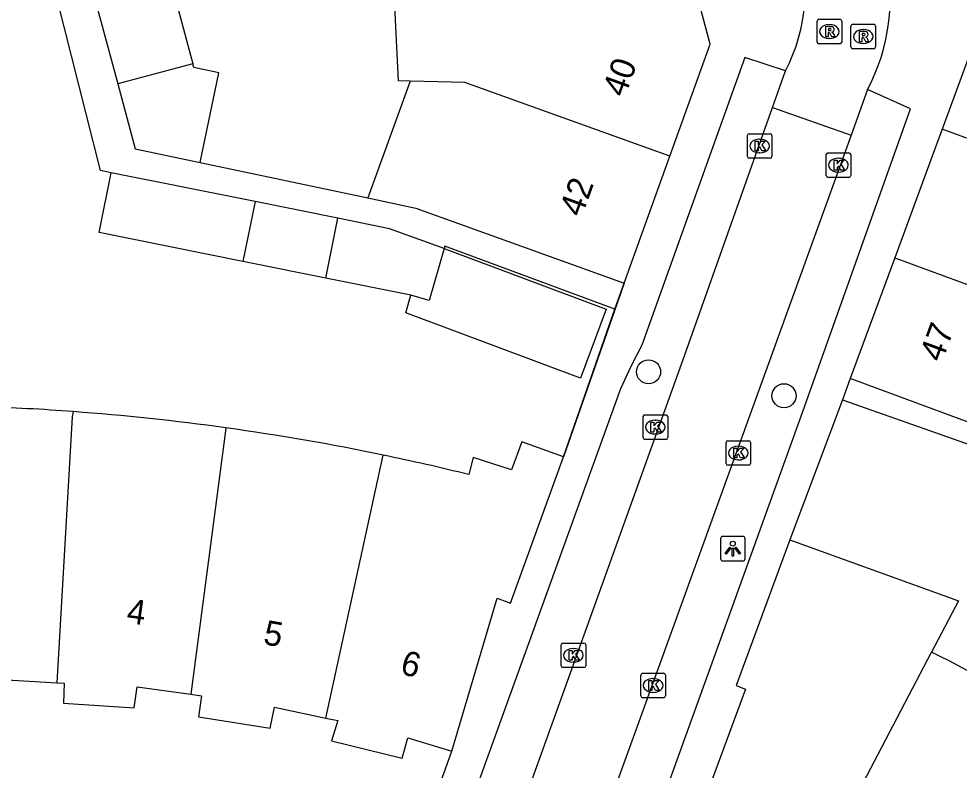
# Model space of a CAD drawing. Extents: x 162542 to 163144, y 380786 to 381511.
# Drawn here: x 162675.46 to 162713.73, y 380871.24 to 380901.83 of the extents above; entities that cross this region are included whole.
import ezdxf

# ---------------------------------------------------------------- set-up
doc = ezdxf.new("R2010")
doc.units = 0
for name, color, linetype in [('IMGEO_Boom', 7, 'Continuous'), ('IMGEO_Kolk', 7, 'Continuous'), ('IMGEO_Lichtpunt', 7, 'Continuous'), ('IMGEO_Muur', 7, 'Continuous'), ('IMGEO_Pand', 7, 'Continuous'), ('IMGEO_Pand_nummerreeks', 7, 'Continuous'), ('IMGEO_Rijbaan_lokaal_open', 7, 'Continuous'), ('IMGEO_Rioolput', 7, 'Continuous'), ('IMGEO_Voetpad_open', 7, 'Continuous')]:
    doc.layers.add(name, color=color, linetype=linetype)

msp = doc.modelspace()

# ---------------------------------------------------------------- linework, layer by layer
at = {"layer": 'IMGEO_Boom'}
for centre in [(162701.087, 380887.461), (162706.598, 380886.486)]:
    msp.add_circle(centre, 0.489, dxfattribs=at)
at = {"layer": 'IMGEO_Kolk'}
for p, q in [((162705.107, 380896.227), (162705.107, 380897.079)), ((162705.182, 380897.153), (162706.034, 380897.153)), ((162705.595, 380896.933), (162705.62, 380896.933)), ((162706.108, 380897.079), (162706.108, 380896.227)), ((162706.034, 380896.153), (162705.182, 380896.153)), ((162705.618, 380896.373), (162705.593, 380896.373)), ((162708.313, 380895.448), (162708.313, 380896.3)), ((162708.388, 380896.374), (162709.24, 380896.374)), ((162708.801, 380896.154), (162708.826, 380896.154)), ((162709.314, 380896.3), (162709.314, 380895.448)), ((162709.24, 380895.374), (162708.388, 380895.374)), ((162708.824, 380895.594), (162708.799, 380895.594)), ((162700.864, 380884.783), (162700.864, 380885.635)), ((162700.939, 380885.709), (162701.791, 380885.709)), ((162701.352, 380885.489), (162701.377, 380885.489)), ((162701.865, 380885.635), (162701.865, 380884.783)), ((162701.791, 380884.709), (162700.939, 380884.709)), ((162701.375, 380884.929), (162701.35, 380884.929)), ((162704.239, 380883.729), (162704.239, 380884.581)), ((162704.314, 380884.655), (162705.166, 380884.655)), ((162705.24, 380884.581), (162705.24, 380883.729)), ((162704.727, 380884.435), (162704.752, 380884.435)), ((162704.75, 380883.875), (162704.725, 380883.875)), ((162705.166, 380883.655), (162704.314, 380883.655)), ((162697.529, 380875.494), (162697.529, 380876.346)), ((162697.604, 380876.42), (162698.456, 380876.42)), ((162698.017, 380876.2), (162698.042, 380876.2)), ((162698.53, 380876.346), (162698.53, 380875.494)), ((162698.456, 380875.42), (162697.604, 380875.42)), ((162698.04, 380875.64), (162698.015, 380875.64)), ((162700.774, 380874.267), (162700.774, 380875.119)), ((162700.849, 380875.193), (162701.701, 380875.193)), ((162701.775, 380875.119), (162701.775, 380874.267)), ((162701.262, 380874.973), (162701.287, 380874.973)), ((162701.285, 380874.413), (162701.26, 380874.413)), ((162701.701, 380874.193), (162700.849, 380874.193))]:
    msp.add_line(p, q, dxfattribs=at)
for points in [[(162705.107, 380896.227), (162705.107, 380897.079)], [(162705.182, 380897.153), (162706.034, 380897.153)], [(162705.428, 380896.853), (162705.551, 380896.853), (162705.551, 380896.702), (162705.681, 380896.853), (162705.845, 380896.853), (162705.699, 380896.702), (162705.852, 380896.453), (162705.7, 380896.453), (162705.615, 380896.617), (162705.551, 380896.55), (162705.551, 380896.453), (162705.428, 380896.453), (162705.428, 380896.853)], [(162706.108, 380897.079), (162706.108, 380896.227)], [(162706.034, 380896.153), (162705.182, 380896.153)], [(162708.313, 380895.448), (162708.313, 380896.3)], [(162708.388, 380896.374), (162709.24, 380896.374)], [(162708.634, 380896.074), (162708.757, 380896.074), (162708.757, 380895.923), (162708.887, 380896.074), (162709.051, 380896.074), (162708.905, 380895.923), (162709.058, 380895.674), (162708.906, 380895.674), (162708.821, 380895.838), (162708.757, 380895.771), (162708.757, 380895.674), (162708.634, 380895.674), (162708.634, 380896.074)], [(162709.314, 380896.3), (162709.314, 380895.448)], [(162709.24, 380895.374), (162708.388, 380895.374)], [(162700.864, 380884.783), (162700.864, 380885.635)], [(162700.939, 380885.709), (162701.791, 380885.709)], [(162701.185, 380885.409), (162701.308, 380885.409), (162701.308, 380885.258), (162701.438, 380885.409), (162701.602, 380885.409), (162701.456, 380885.258), (162701.609, 380885.009), (162701.457, 380885.009), (162701.372, 380885.173), (162701.308, 380885.106), (162701.308, 380885.009), (162701.185, 380885.009), (162701.185, 380885.409)], [(162701.865, 380885.635), (162701.865, 380884.783)], [(162701.791, 380884.709), (162700.939, 380884.709)], [(162704.239, 380883.729), (162704.239, 380884.581)], [(162704.314, 380884.655), (162705.166, 380884.655)], [(162705.24, 380884.581), (162705.24, 380883.729)], [(162704.56, 380884.355), (162704.683, 380884.355), (162704.683, 380884.204), (162704.813, 380884.355), (162704.977, 380884.355), (162704.831, 380884.204), (162704.984, 380883.955), (162704.832, 380883.955), (162704.747, 380884.119), (162704.683, 380884.052), (162704.683, 380883.955), (162704.56, 380883.955), (162704.56, 380884.355)], [(162705.166, 380883.655), (162704.314, 380883.655)], [(162697.529, 380875.494), (162697.529, 380876.346)], [(162697.604, 380876.42), (162698.456, 380876.42)], [(162698.53, 380876.346), (162698.53, 380875.494)], [(162697.85, 380876.12), (162697.973, 380876.12), (162697.973, 380875.969), (162698.103, 380876.12), (162698.267, 380876.12), (162698.121, 380875.969), (162698.274, 380875.72), (162698.122, 380875.72), (162698.037, 380875.884), (162697.973, 380875.817), (162697.973, 380875.72), (162697.85, 380875.72), (162697.85, 380876.12)], [(162698.456, 380875.42), (162697.604, 380875.42)], [(162700.774, 380874.267), (162700.774, 380875.119)], [(162700.849, 380875.193), (162701.701, 380875.193)], [(162701.775, 380875.119), (162701.775, 380874.267)], [(162701.095, 380874.893), (162701.218, 380874.893), (162701.218, 380874.742), (162701.348, 380874.893), (162701.512, 380874.893), (162701.366, 380874.742), (162701.519, 380874.493), (162701.367, 380874.493), (162701.282, 380874.657), (162701.218, 380874.59), (162701.218, 380874.493), (162701.095, 380874.493), (162701.095, 380874.893)], [(162701.701, 380874.193), (162700.849, 380874.193)]]:
    msp.add_lwpolyline(points, dxfattribs=at)
for centre, start, end in [((162705.184, 380897.077), 91.552, 178.448), ((162705.184, 380897.077), 91.552, 178.448), ((162706.032, 380897.077), 1.552, 88.448), ((162706.032, 380897.077), 1.552, 88.448), ((162705.184, 380896.229), 181.552, 268.448), ((162705.184, 380896.229), 181.552, 268.448), ((162706.032, 380896.229), 271.552, 358.448), ((162706.032, 380896.229), 271.552, 358.448), ((162708.39, 380896.298), 91.552, 178.448), ((162708.39, 380896.298), 91.552, 178.448), ((162709.238, 380896.298), 1.552, 88.448), ((162709.238, 380896.298), 1.552, 88.448), ((162708.39, 380895.45), 181.552, 268.448), ((162708.39, 380895.45), 181.552, 268.448), ((162709.238, 380895.45), 271.552, 358.448), ((162709.238, 380895.45), 271.552, 358.448), ((162700.941, 380885.633), 91.552, 178.448), ((162700.941, 380885.633), 91.552, 178.448), ((162701.789, 380885.633), 1.552, 88.448), ((162701.789, 380885.633), 1.552, 88.448), ((162700.941, 380884.785), 181.552, 268.448), ((162700.941, 380884.785), 181.552, 268.448), ((162701.789, 380884.785), 271.552, 358.448), ((162701.789, 380884.785), 271.552, 358.448), ((162704.316, 380884.579), 91.552, 178.448), ((162704.316, 380884.579), 91.552, 178.448), ((162705.164, 380884.579), 1.552, 88.448), ((162705.164, 380884.579), 1.552, 88.448), ((162704.316, 380883.731), 181.552, 268.448), ((162704.316, 380883.731), 181.552, 268.448), ((162705.164, 380883.731), 271.552, 358.448), ((162705.164, 380883.731), 271.552, 358.448), ((162697.606, 380876.344), 91.552, 178.448), ((162697.606, 380876.344), 91.552, 178.448), ((162698.454, 380876.344), 1.552, 88.448), ((162698.454, 380876.344), 1.552, 88.448), ((162697.606, 380875.496), 181.552, 268.448), ((162697.606, 380875.496), 181.552, 268.448), ((162698.454, 380875.496), 271.552, 358.448), ((162698.454, 380875.496), 271.552, 358.448), ((162700.851, 380875.117), 91.552, 178.448), ((162700.851, 380875.117), 91.552, 178.448), ((162701.699, 380875.117), 1.552, 88.448), ((162701.699, 380875.117), 1.552, 88.448), ((162700.851, 380874.269), 181.552, 268.448), ((162700.851, 380874.269), 181.552, 268.448), ((162701.699, 380874.269), 271.552, 358.448), ((162701.699, 380874.269), 271.552, 358.448)]:
    msp.add_arc(centre, 0.0765, start, end, dxfattribs=at)
for centre, major_axis, ratio, start_param, end_param in [((162705.594, 380896.653), (-0.387, 0.002), 0.722429, 4.712389, 7.853982), ((162705.619, 380896.653), (-0.39, 0.002), 0.717154, 1.570796, 4.712389), ((162708.8, 380895.874), (-0.387, 0.002), 0.722429, 4.712389, 7.853982), ((162708.825, 380895.874), (-0.39, 0.002), 0.717154, 1.570796, 4.712389), ((162701.351, 380885.209), (-0.387, 0.002), 0.722429, 4.712389, 7.853982), ((162701.376, 380885.209), (-0.39, 0.002), 0.717154, 1.570796, 4.712389), ((162704.726, 380884.155), (-0.387, 0.002), 0.722429, 4.712389, 7.853982), ((162704.751, 380884.155), (-0.39, 0.002), 0.717154, 1.570796, 4.712389), ((162698.016, 380875.92), (-0.387, 0.002), 0.722429, 4.712389, 7.853982), ((162698.041, 380875.92), (-0.39, 0.002), 0.717154, 1.570796, 4.712389), ((162701.261, 380874.693), (-0.387, 0.002), 0.722429, 4.712389, 7.853982), ((162701.286, 380874.693), (-0.39, 0.002), 0.717154, 1.570796, 4.712389)]:
    msp.add_ellipse(centre, major_axis=major_axis, ratio=ratio, start_param=start_param, end_param=end_param, dxfattribs=at)
at = {"layer": 'IMGEO_Lichtpunt'}
for p, q in [((162704.917, 380880.76), (162704.109, 380880.76)), ((162704.917, 380880.76), (162704.109, 380880.76)), ((162704.015, 380880.665), (162704.015, 380879.858)), ((162704.015, 380880.665), (162704.015, 380879.858)), ((162705.011, 380879.858), (162705.011, 380880.665)), ((162705.011, 380879.858), (162705.011, 380880.665)), ((162704.109, 380879.764), (162704.917, 380879.764)), ((162704.109, 380879.764), (162704.917, 380879.764))]:
    msp.add_line(p, q, dxfattribs=at)
for points in [[(162704.389, 380880.329), (162704.428, 380880.301), (162704.24, 380880.039), (162704.202, 380880.066), (162704.389, 380880.329)], [(162704.491, 380880.281), (162704.538, 380880.281), (162704.538, 380879.959), (162704.491, 380879.959), (162704.491, 380880.281)], [(162704.601, 380880.301), (162704.639, 380880.328), (162704.826, 380880.066), (162704.787, 380880.038), (162704.601, 380880.301)]]:
    msp.add_lwpolyline(points, dxfattribs=at)
msp.add_circle((162704.514, 380880.463), 0.0994, dxfattribs=at)
for centre, start, end in [((162704.109, 380880.665), 90, 180), ((162704.109, 380880.665), 90, 180), ((162704.917, 380880.665), 0, 90), ((162704.917, 380880.665), 0, 90), ((162704.109, 380879.858), 180, 270), ((162704.109, 380879.858), 180, 270), ((162704.917, 380879.858), 270, 0), ((162704.917, 380879.858), 270, 360)]:
    msp.add_arc(centre, 0.0946, start, end, dxfattribs=at)
at = {"layer": 'IMGEO_Muur'}
for points in [[(162700.089, 380891.066), (162697.624, 380884.004)], [(162709.296, 380887.183), (162708.973, 380886.322)], [(162708.973, 380886.322), (162706.835, 380880.62)]]:
    msp.add_lwpolyline(points, dxfattribs=at)
at = {"layer": 'IMGEO_Pand'}
for points in [[(162701.953, 380896.238), (162703.596, 380900.795), (162702.381, 380905.324)], [(162680.618, 380904.97), (162681.363, 380904.413), (162682.545, 380900.004)], [(162678.116, 380904.298), (162679.487, 380899.184)], [(162714.848, 380903.523), (162715.042, 380902.802), (162713.032, 380897.337)], [(162691.381, 380899.298), (162690.914, 380899.31), (162690.755, 380902.634), (162691.216, 380902.744), (162692.974, 380903.163)], [(162682.545, 380900.004), (162679.487, 380899.184)], [(162682.838, 380895.98), (162683.609, 380899.636), (162682.586, 380899.852), (162682.545, 380900.004)], [(162679.487, 380899.184), (162680.196, 380896.538), (162682.838, 380895.98)], [(162691.381, 380899.298), (162689.669, 380894.546)], [(162701.953, 380896.238), (162693.611, 380899.243), (162691.381, 380899.298)], [(162713.032, 380897.337), (162712.628, 380896.238), (162711.106, 380892.104)], [(162721.674, 380894.157), (162713.032, 380897.337)], [(162700.089, 380891.066), (162701.953, 380896.238)], [(162684.585, 380891.957), (162678.737, 380893.135), (162679.227, 380895.564)], [(162685.075, 380894.387), (162679.227, 380895.564)], [(162689.669, 380894.546), (162691.622, 380894.118), (162695.386, 380892.761), (162700.089, 380891.066)], [(162685.075, 380894.387), (162684.585, 380891.957)], [(162688.442, 380893.709), (162685.075, 380894.387)], [(162687.952, 380891.279), (162688.442, 380893.709)], [(162692.773, 380892.484), (162690.547, 380893.285), (162688.442, 380893.709)], [(162692.773, 380892.484), (162699.368, 380890.014), (162698.317, 380887.206), (162691.209, 380889.867), (162691.411, 380890.575)], [(162692.773, 380892.484), (162692.167, 380890.359), (162691.411, 380890.575)], [(162687.952, 380891.279), (162684.585, 380891.957)], [(162711.106, 380892.104), (162709.296, 380887.183)], [(162711.106, 380892.104), (162719.749, 380888.925)], [(162691.411, 380890.575), (162687.952, 380891.279)], [(162717.938, 380884.003), (162713.989, 380885.456), (162709.296, 380887.183)], [(162677.673, 380885.841), (162677.633, 380885.626), (162677.006, 380874.805)], [(162683.894, 380885.179), (162683.877, 380885.054), (162682.461, 380874.335)], [(162697.624, 380884.004), (162695.932, 380884.614), (162695.507, 380883.468), (162693.951, 380883.967), (162693.768, 380883.278)], [(162687.958, 380873.364), (162690.29, 380884.07)], [(162693.08, 380872.013), (162694.93, 380878.241), (162695.475, 380878.043), (162697.624, 380884.004)], [(162706.835, 380880.62), (162704.652, 380874.688), (162705.03, 380874.549), (162702.812, 380868.521)], [(162706.835, 380880.62), (162713.691, 380878.134), (162712.602, 380876.05)], [(162707.504, 380866.291), (162712.602, 380876.05)], [(162671.383, 380874.988), (162671.837, 380875.008), (162671.862, 380874.138), (162674.75, 380874.121), (162674.764, 380874.941), (162677.006, 380874.805)], [(162677.006, 380874.805), (162677.312, 380874.786), (162677.277, 380873.977), (162680.155, 380873.78), (162680.28, 380874.639), (162682.461, 380874.335)], [(162682.461, 380874.335), (162682.896, 380874.274), (162682.771, 380873.415), (162685.697, 380872.957), (162685.871, 380873.806), (162687.958, 380873.364)], [(162687.958, 380873.364), (162688.447, 380873.261), (162688.193, 380872.443), (162691.057, 380871.736), (162691.291, 380872.555), (162693.08, 380872.013)]]:
    msp.add_lwpolyline(points, dxfattribs=at)
for centre, radius, start, end in [((162670.599, 380789.961), 96.141, 85.78058, 87.99975), ((162670.494, 380788.819), 97.287, 82.08325, 85.76835), ((162670.509, 380788.987), 97.119, 78.24812, 82.07849), ((162670.614, 380789.632), 96.466, 76.11215, 78.2309), ((162681.898, 380814.678), 68.624, 58.09881, 63.42173)]:
    msp.add_arc(centre, radius, start, end, dxfattribs=at)
at = {"layer": 'IMGEO_Rijbaan_lokaal_open'}
for points in [[(162706.129, 380898.216), (162706.661, 380899.718)], [(162709.996, 380898.948), (162709.326, 380897.095)], [(162693.885, 380863.997), (162702.496, 380887.96), (162706.129, 380898.216)], [(162706.129, 380898.216), (162709.326, 380897.095)], [(162709.326, 380897.095), (162696.974, 380862.936)]]:
    msp.add_lwpolyline(points, dxfattribs=at)
for centre, radius, start, end in [((162700.573, 380902.918), 6.878, 332.274, 19.9732), ((162702.814, 380902.728), 8.116, 332.2394, 12.2618)]:
    msp.add_arc(centre, radius, start, end, dxfattribs=at)
at = {"layer": 'IMGEO_Rioolput'}
for p, q in [((162708.019, 380901.812), (162708.871, 380901.812)), ((162707.944, 380900.886), (162707.944, 380901.738)), ((162708.432, 380901.592), (162708.457, 380901.592)), ((162708.945, 380901.738), (162708.945, 380900.886)), ((162709.321, 380900.684), (162709.321, 380901.536)), ((162709.396, 380901.61), (162710.248, 380901.61)), ((162710.322, 380901.536), (162710.322, 380900.684)), ((162708.455, 380901.032), (162708.43, 380901.032)), ((162709.809, 380901.39), (162709.834, 380901.39)), ((162708.871, 380900.812), (162708.019, 380900.812)), ((162709.832, 380900.83), (162709.807, 380900.83)), ((162710.248, 380900.61), (162709.396, 380900.61))]:
    msp.add_line(p, q, dxfattribs=at)
for points in [[(162708.019, 380901.812), (162708.871, 380901.812)], [(162707.944, 380900.886), (162707.944, 380901.738)], [(162708.533, 380901.51), (162708.281, 380901.512), (162708.281, 380901.112)], [(162708.459, 380901.431), (162708.405, 380901.431), (162708.405, 380901.35)], [(162708.945, 380901.738), (162708.945, 380900.886)], [(162709.321, 380900.684), (162709.321, 380901.536)], [(162709.396, 380901.61), (162710.248, 380901.61)], [(162710.322, 380901.536), (162710.322, 380900.684)], [(162708.281, 380901.112), (162708.405, 380901.112), (162708.405, 380901.274), (162708.416, 380901.274)], [(162708.405, 380901.35), (162708.457, 380901.35)], [(162708.463, 380901.245), (162708.534, 380901.112), (162708.674, 380901.112), (162708.609, 380901.238)], [(162709.91, 380901.308), (162709.658, 380901.31), (162709.658, 380900.91)], [(162709.658, 380900.91), (162709.782, 380900.91), (162709.782, 380901.072), (162709.793, 380901.072)], [(162709.836, 380901.229), (162709.782, 380901.229), (162709.782, 380901.148)], [(162709.782, 380901.148), (162709.834, 380901.148)], [(162709.84, 380901.043), (162709.911, 380900.91), (162710.051, 380900.91), (162709.986, 380901.036)], [(162708.871, 380900.812), (162708.019, 380900.812)], [(162710.248, 380900.61), (162709.396, 380900.61)]]:
    msp.add_lwpolyline(points, dxfattribs=at)
for centre, radius, start, end in [((162708.021, 380901.736), 0.0765, 91.552, 178.448), ((162708.021, 380901.736), 0.0765, 91.552, 178.448), ((162708.869, 380901.736), 0.0765, 1.552, 88.448), ((162708.869, 380901.736), 0.0765, 1.552, 88.448), ((162708.465, 380901.335), 0.0964, 77.0061, 93.1865), ((162708.479, 380901.392), 0.0378, 276.6634, 79.6772), ((162708.532, 380901.4), 0.109, 350.3612, 89.416), ((162709.398, 380901.534), 0.0765, 91.552, 178.448), ((162709.398, 380901.534), 0.0765, 91.552, 178.448), ((162710.246, 380901.534), 0.0765, 1.552, 88.448), ((162710.246, 380901.534), 0.0765, 1.552, 88.448), ((162708.415, 380901.221), 0.0533, 26.0293, 88.6989), ((162708.441, 380901.539), 0.19, 274.7715, 282.9687), ((162708.53, 380901.4), 0.112, 277.5842, 350.9817), ((162708.514, 380901.185), 0.108, 29.5134, 73.7905), ((162709.792, 380901.019), 0.0533, 26.0293, 88.6989), ((162709.818, 380901.337), 0.19, 274.7715, 282.9687), ((162709.842, 380901.133), 0.0964, 77.0061, 93.1865), ((162709.856, 380901.19), 0.0378, 276.6634, 79.6772), ((162709.909, 380901.198), 0.109, 350.3612, 89.416), ((162709.907, 380901.198), 0.112, 277.5842, 350.9817), ((162709.891, 380900.983), 0.108, 29.5134, 73.7905), ((162708.021, 380900.888), 0.0765, 181.552, 268.448), ((162708.021, 380900.888), 0.0765, 181.552, 268.448), ((162708.869, 380900.888), 0.0765, 271.552, 358.448), ((162708.869, 380900.888), 0.0765, 271.552, 358.448), ((162709.398, 380900.686), 0.0765, 181.552, 268.448), ((162709.398, 380900.686), 0.0765, 181.552, 268.448), ((162710.246, 380900.686), 0.0765, 271.552, 358.448), ((162710.246, 380900.686), 0.0765, 271.552, 358.448)]:
    msp.add_arc(centre, radius, start, end, dxfattribs=at)
for centre, major_axis, ratio, start_param, end_param in [((162708.431, 380901.312), (-0.387, 0.002), 0.722429, 4.712389, 7.853982), ((162708.456, 380901.312), (-0.39, 0.002), 0.717154, 1.570796, 4.712389), ((162709.808, 380901.11), (-0.387, 0.002), 0.722429, 4.712389, 7.853982), ((162709.833, 380901.11), (-0.39, 0.002), 0.717154, 1.570796, 4.712389)]:
    msp.add_ellipse(centre, major_axis=major_axis, ratio=ratio, start_param=start_param, end_param=end_param, dxfattribs=at)
at = {"layer": 'IMGEO_Voetpad_open'}
for points in [[(162679.227, 380895.564), (162678.782, 380895.654), (162675.825, 380907.372)], [(162706.661, 380899.718), (162705.001, 380900.259), (162700.819, 380888.55), (162700.368, 380887.677), (162699.947, 380886.774), (162692.258, 380865.461)], [(162699.106, 380862.935), (162707.301, 380885.65), (162711.741, 380898.166), (162709.996, 380898.948)], [(162682.838, 380895.98), (162689.669, 380894.546)], [(162699.719, 380890.006), (162692.801, 380892.571), (162692.773, 380892.484)], [(162699.719, 380890.006), (162700.089, 380891.066)], [(162697.624, 380884.004), (162699.719, 380890.006)], [(162709.296, 380887.183), (162708.973, 380886.322)], [(162708.973, 380886.322), (162706.835, 380880.62)], [(162708.973, 380886.322), (162715.368, 380884.061), (162719.996, 380882.402), (162723.849, 380881.02), (162728.902, 380879.209), (162729.699, 380878.442)], [(162691.344, 380867.183), (162693.08, 380872.013)]]:
    msp.add_lwpolyline(points, dxfattribs=at)

# ---------------------------------------------------------------- texts
at = {"layer": 'IMGEO_Pand_nummerreeks'}
for s, rotation, p in [('40', 70.1759, (162700.124, 380898.597)), ('42', 70.1807, (162698.369, 380893.726)), ('47', 69.7997, (162713.023, 380887.813)), ('4', 352.057, (162679.818, 380877.248)), ('5', 349.9903, (162685.376, 380876.378)), ('6', 345.1852, (162690.94, 380875.182))]:
    msp.add_text(s, height=1, rotation=rotation, dxfattribs=at).set_placement(p)

doc.saveas('drawing.dxf')
